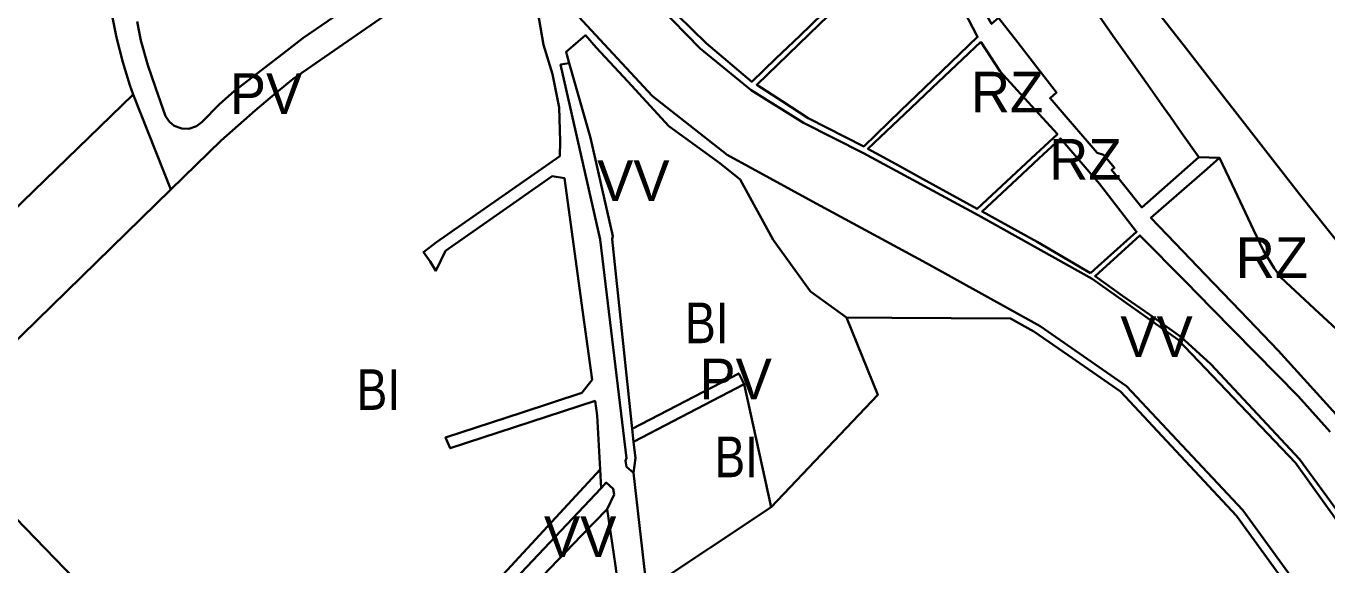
# Model space of a CAD drawing. Extents: x -650451 to -642268, y -1075216 to -1066610.
# Drawn here: x -646557.7 to -646077.2, y -1072495.7 to -1072296.6 of the extents above; entities that cross this region are included whole.
import ezdxf

# ---------------------------------------------------------------- set-up
doc = ezdxf.new("R2010")
doc.units = 0
doc.header["$LTSCALE"] = 6
doc.layers.add('1', color=7, linetype='Continuous', lineweight=35)
doc.layers.add('2', color=7, linetype='Continuous')
doc.layers.add('3', color=7, linetype='Continuous')

msp = doc.modelspace()

# ---------------------------------------------------------------- linework, layer by layer
at = {"layer": '1'}
for p, q in [((-646504.244, -1072357.026), (-646518.208, -1072321.92)), ((-646137.35, -1072326.93), (-646135.06, -1072330.21)), ((-646135.06, -1072330.21), (-646130.92, -1072336.06)), ((-646130.92, -1072336.06), (-646124.57, -1072345.05)), ((-646096.74, -1072386.1), (-646094.3, -1072389.47)), ((-646333.33, -1072450.12), (-646292.44, -1072428.89)), ((-646282.47, -1072474.34), (-646292.44, -1072428.89)), ((-646333.84, -1072445.32), (-646333.33, -1072450.12)), ((-646345.36, -1072467.29), (-646345.741, -1072460.38)), ((-646333.34, -1072461.67), (-646328.45, -1072504.81)), ((-646282.47, -1072474.34), (-646328.45, -1072504.81))]:
    msp.add_line(p, q, dxfattribs=at)
for points in [[(-646000.45, -1072615.28), (-645999.14, -1072611.29), (-646006.21, -1072593.04), (-646009.27, -1072582.89), (-646016.46, -1072568.07), (-646027.37, -1072549.05), (-646034.83, -1072536.97), (-646054.33, -1072506.16), (-646088.86, -1072457.93), (-646132.34, -1072412.37), (-646164.02, -1072390), (-646206.07, -1072366.43), (-646248.46, -1072343.52), (-646270.62, -1072332.33), (-646289.9, -1072320.26), (-646308.74, -1072304.97), (-646324.17, -1072289.15), (-646339.07, -1072270.33), (-646350.46, -1072250.81), (-646370.83, -1072206.8), (-646394.24, -1072163.81), (-646419.55, -1072128.03), (-646512.21, -1072052.57)], [(-646518.208, -1072321.92), (-646587.666, -1072389.082), (-646606.848, -1072405.785), (-646712.634, -1072292.59), (-646555.051, -1072174.933)], [(-646555.051, -1072174.933), (-646554.56, -1072175.629), (-646549.793, -1072183.38), (-646546.09, -1072190.428), (-646542.484, -1072197.985), (-646539.168, -1072206.122), (-646536.772, -1072213.218), (-646535.344, -1072217.844), (-646533.286, -1072226.031), (-646531.93, -1072232.861), (-646530.892, -1072239.747), (-646530.188, -1072247.442), (-646529.182, -1072265.941), (-646528.566, -1072273.308), (-646527.5, -1072282.657), (-646526, -1072292.201), (-646524.282, -1072300.849), (-646522.007, -1072309.932), (-646519.417, -1072318.408), (-646518.208, -1072321.92)], [(-645943.65, -1072789.47), (-645967.22, -1072787.26), (-645967.91, -1072767.31), (-645970.61, -1072747.97), (-645973.9, -1072738.22), (-645989.39, -1072712.38), (-646003.73, -1072680.75), (-646016.23, -1072641.16), (-646028.02, -1072609.24), (-646040.96, -1072577.06), (-646054.2, -1072554.48), (-646073.49, -1072523.45), (-646108.36, -1072475.46), (-646151.34, -1072429.6), (-646183.23, -1072407.45), (-646225.13, -1072384.18), (-646267.31, -1072361.39), (-646298.76, -1072344.13), (-646326.33, -1072322.56), (-646349.05, -1072298.16), (-646356.62, -1072289.89), (-646367.24, -1072276.07), (-646407.81, -1072188.6), (-646415.75, -1072178.82)], [(-646124.57, -1072345.05), (-646145.57, -1072363.62), (-646152.42, -1072355.16), (-646156.78, -1072349.77), (-646155.77, -1072349.02), (-646158.29, -1072345.96), (-646159.76, -1072344.16), (-646162.06, -1072343.4), (-646165.77, -1072339.12), (-646172.77, -1072331.06), (-646179.53, -1072323.27), (-646177.12, -1072321.19), (-646184.36, -1072311.83), (-646191.42, -1072302.72), (-646198.51, -1072293.55), (-646201.14, -1072295.81), (-646206.54, -1072286.21), (-646211.97, -1072276.57), (-646218.5, -1072266.6), (-646224.64, -1072257.23), (-646202.08, -1072235.38)], [(-646380.12, -1072261.44), (-646459.03, -1072316.137), (-646465.227, -1072321.127), (-646473.069, -1072327.765), (-646485.656, -1072338.908), (-646504.244, -1072357.026)], [(-646516.692, -1072294.983), (-646515.305, -1072301.925), (-646512.729, -1072311.048), (-646509.954, -1072319.377), (-646506.189, -1072329.889), (-646504.802, -1072331.971), (-646503.018, -1072333.459), (-646500.244, -1072334.45), (-646497.569, -1072334.55), (-646494.794, -1072333.558), (-646492.813, -1072332.07), (-646486.273, -1072325.526), (-646480.923, -1072320.667), (-646462.79, -1072306.784), (-646455.557, -1072301.131), (-646420.085, -1072276.737)], [(-646167.16, -1072284.79), (-646160.44, -1072294.29), (-646156.16, -1072300.36), (-646149.48, -1072309.81)], [(-646129.15, -1072305.06), (-646135.43, -1072296.99), (-646144.38, -1072285.47), (-646146.27, -1072282.34)], [(-646345.741, -1072460.38), (-646346.84, -1072440.47), (-646347.58, -1072435.06), (-646401.03, -1072452.52), (-646402.86, -1072448.6), (-646374.47, -1072439.32), (-646352.45, -1072432.13), (-646348.65, -1072427.26), (-646352.05, -1072402.47), (-646358.86, -1072352.78), (-646363.44, -1072352.07), (-646383.92, -1072366.41), (-646402.77, -1072379.6), (-646406.36, -1072386.99), (-646408.5, -1072383.61), (-646410.98, -1072380.07), (-646406.17, -1072376.49), (-646360.64, -1072344.62), (-646360.5, -1072339.08), (-646360.84, -1072326.72), (-646363.24, -1072314.34), (-646366.62, -1072303.53), (-646369.35, -1072287.95)], [(-646254.75, -1072404.25), (-646268.05, -1072394.66), (-646281.83, -1072375.54), (-646293.93, -1072353.28), (-646301.43, -1072347.28), (-646320.28, -1072333.64), (-646328.57, -1072324.62), (-646335.52, -1072317.05), (-646347.2, -1072304.53), (-646351.15, -1072300), (-646355.68, -1072303.92), (-646358.28, -1072306.16), (-646358.01, -1072307.07), (-646357.09, -1072310.35)], [(-646071, -1072379.27), (-646087.44, -1072358.73), (-646120.23, -1072316.54), (-646129.15, -1072305.06)], [(-646357.09, -1072310.35), (-646360.3, -1072310.87), (-646345.73, -1072375.51), (-646336.01, -1072456.23), (-646336.29, -1072457.22), (-646335.99, -1072459.38), (-646333.34, -1072461.67)], [(-646357.09, -1072310.35), (-646349.31, -1072337.93), (-646345.6, -1072354.14), (-646341, -1072374.27), (-646341.29, -1072375.31), (-646333.84, -1072445.32)], [(-646149.48, -1072309.81), (-646143.44, -1072318.35), (-646137.35, -1072326.93)], [(-646018.97, -1072490.66), (-646020.51, -1072492.32), (-646027.04, -1072485.99), (-646052.25, -1072461.52), (-646069.15, -1072445.12), (-646071.51, -1072442.7), (-646095.21, -1072416.49), (-646109.15, -1072401.97), (-646122.26, -1072388.32), (-646133.31, -1072376.82), (-646142.28, -1072367.48), (-646121.49, -1072349.32), (-646116.89, -1072345.3)], [(-646124.57, -1072345.05), (-646116.89, -1072345.3), (-646111.23, -1072357.28)], [(-646504.244, -1072357.026), (-646575.792, -1072426.789), (-646594.561, -1072444.38)], [(-646111.23, -1072357.28), (-646104.34, -1072371.88), (-646100.79, -1072379.38), (-646096.74, -1072386.1)], [(-646076.12, -1072446.48), (-646087.86, -1072433.28), (-646119.73, -1072400.93), (-646129.51, -1072391.01), (-646146.33, -1072373.93), (-646162.91, -1072388.99), (-646152.72, -1072396.2), (-646142.81, -1072403.2), (-646131.25, -1072411.38), (-646120.15, -1072421.49), (-646109.85, -1072432.52), (-646087.36, -1072456.59), (-646077.32, -1072470.36), (-646067.89, -1072483.29)], [(-646094.3, -1072389.47), (-646080.11, -1072402.61), (-646064.38, -1072417.18), (-646050.33, -1072430.19), (-646003.3, -1072473.75), (-646008.32, -1072479.17)], [(-646254.75, -1072404.25), (-646243.17, -1072432.88), (-646282.47, -1072474.34)], [(-646075.82, -1072525.54), (-646110.61, -1072477.49), (-646153.49, -1072431.54), (-646172.81, -1072418.2), (-646185.45, -1072409.47), (-646194.19, -1072404.62), (-646237.94, -1072404.35), (-646254.75, -1072404.25)], [(-646292.44, -1072428.89), (-646294.51, -1072424.9), (-646333.84, -1072445.32)], [(-646345.741, -1072460.38), (-646389.081, -1072507.297), (-646445.877, -1072566.771), (-646459.575, -1072583.748), (-646594.561, -1072444.38)], [(-646333.33, -1072450.12), (-646332.68, -1072456.19), (-646333.34, -1072461.67)], [(-646464.22, -1072595.84), (-646442.31, -1072569.97), (-646425.07, -1072551.7), (-646392.36, -1072517.06), (-646385.5, -1072509.78), (-646345.36, -1072467.29)], [(-646345.36, -1072467.29), (-646343.44, -1072465.25), (-646340.83, -1072467.49), (-646340.51, -1072469.67), (-646343.13, -1072475.03)], [(-646343.13, -1072475.03), (-646352.53, -1072484.78), (-646372.79, -1072505.81), (-646381.81, -1072515.17), (-646384.41, -1072517.86), (-646395.71, -1072529.8), (-646419.42, -1072554.86)], [(-646419.42, -1072554.86), (-646417.04, -1072558.03), (-646389.66, -1072542.34), (-646375.02, -1072533.97), (-646366.06, -1072528.72), (-646361.21, -1072525.88), (-646350.3, -1072517.64), (-646349.44, -1072516.94), (-646346.96, -1072514.94), (-646344.62, -1072513.04), (-646342.09, -1072511), (-646340.7, -1072509.87), (-646338.39, -1072508), (-646339.97, -1072495.95), (-646343.13, -1072475.03)]]:
    msp.add_lwpolyline(points, dxfattribs=at)
for points in [[(-646257.17, -1072225.02), (-646243.64, -1072243.12), (-646230.6, -1072260.59), (-646237.45, -1072267.15), (-646254.8, -1072283.76), (-646263.55, -1072292.13), (-646271.98, -1072300.2), (-646280.78, -1072308.62), (-646289.72, -1072317.17), (-646306.56, -1072302.91), (-646322.37, -1072287.43), (-646311.21, -1072276.74), (-646302.49, -1072268.4), (-646293.54, -1072259.83), (-646285.1, -1072251.76), (-646276.46, -1072243.48), (-646267.59, -1072235)], [(-646229.47, -1072262.11), (-646216.82, -1072280.7), (-646211.41, -1072290.93), (-646206.31, -1072300.61), (-646225.91, -1072319.47), (-646234.63, -1072327.85), (-646248.36, -1072341.06), (-646268.81, -1072330.59), (-646278.46, -1072324.39), (-646287.88, -1072318.32), (-646264.64, -1072295.96), (-646256.03, -1072287.68), (-646247.38, -1072279.35)], [(-646205.12, -1072302.43), (-646197.91, -1072313.41), (-646191.63, -1072320.28), (-646176.79, -1072336.5), (-646184.82, -1072343.99), (-646201.02, -1072359.11), (-646206.45, -1072364.17), (-646226.6, -1072353.06), (-646236.62, -1072347.54), (-646246.79, -1072341.94), (-646230.97, -1072326.94), (-646223.02, -1072319.41)], [(-646164.58, -1072387.87), (-646161.82, -1072385.4), (-646147.55, -1072372.6), (-646161.23, -1072354.91), (-646175.69, -1072338.14), (-646183.61, -1072345.52), (-646191.79, -1072353.13), (-646204.61, -1072365.07), (-646184.28, -1072376.27)]]:
    msp.add_lwpolyline(points, close=True, dxfattribs=at)

# ---------------------------------------------------------------- texts
at = {"layer": '2'}
for s, p in [('RZ', (-646208.787, -1072328.503)), ('RZ', (-646179.885, -1072353.329)), ('VV', (-646346.809, -1072361.182)), ('RZ', (-646110.966, -1072389.64)), ('VV', (-646153.569, -1072418.791)), ('PV', (-646309.026, -1072434.459)), ('VV', (-646366.448, -1072492.729))]:
    msp.add_text(s, height=15, dxfattribs=at).set_placement(p)
at = {"layer": '2', "width": 0.85}
for p in [(-646314.351, -1072413.756), (-646435.67, -1072438.39)]:
    msp.add_text('BI', height=15, dxfattribs=at).set_placement(p)
at = {"layer": '3'}
msp.add_text('PV', height=15, dxfattribs=at).set_placement((-646482.489, -1072329.048))
at = {"layer": '3', "width": 0.85}
msp.add_text('BI', height=15, dxfattribs=at).set_placement((-646303.486, -1072463.255))

doc.saveas('drawing.dxf')
